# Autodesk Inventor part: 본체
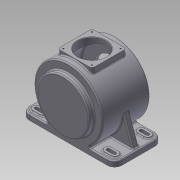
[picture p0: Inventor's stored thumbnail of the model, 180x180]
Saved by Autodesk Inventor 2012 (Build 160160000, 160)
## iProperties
Created: 2015-06
Part Number: 본체
Material: 알루미늄-6061
Document SubType Name: Modeling
Designer: Administrator
Density: 2.71 g/cm^3
Mass: 3279.03 g
Surface Area: 2317.29 cm^2
Volume: 1209.97 cm^3
Author: Administrator
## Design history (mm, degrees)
sketch "스케치1"
  geometry: L1 (0, -59)-(115, -59); L2 (115, -59)-(115, 59); L3 (115, 59)-(-115, 59); L4 (-115, 59)-(-115, -59); L5 (-115, -59)-(0, -59); 1 further point
  constraints: 10 end point, 1 collinear, 1 parallel, 1 perpendicular, 1 point on line
  dimensions: "d7" = 118 distance of L1.end L2.end; "d8" = 230 distance of L2.end L3.end; "d9" = 118 distance of L3.end L4.end
extrude "돌출1" new body sketch "스케치1" distance "d10" = 14; taper "d11" = 0 deg
sketch "스케치2"
  geometry: C1 r 85 at (0, 85); 1 further point
  constraints: 1 centre point
  dimensions: "d13" = 170 diameter of C1
extrude "돌출2" join sketch "스케치2" stored distance "d14" = 118; taper "d15" = 0 deg
sketch "스케치3"
  geometry: C1 r 77 at (0, 85); 1 further point
  constraints: 1 centre point
extrude "돌출3" cut sketch "스케치3" stored distance "d20" = 102; taper "d21" = 0 deg
sketch "스케치4"
  geometry: C1 r 65 at (115, -85); A1 r 85 centre (115, -85) between (68.267, -14) and (161.733, -14) reference; 1 further point
  constraints: 1 centre point, 1 coincident
  dimensions: "d22" = 130 diameter of C1
extrude "돌출4" join sketch "스케치4" distance "d23" = 3; taper "d24" = 0 deg
sketch "스케치5"
  geometry: C1 r 65 at (0, 0) reference; C2 r 47.5 at (0, 0); 1 further point
  constraints: 1 centre point, 1 coincident
  dimensions: "d25" = 95 diameter of C2
extrude "돌출5" cut sketch "스케치5" distance "d26" = 30; taper "d27" = 0 deg
sketch "스케치6"
  geometry: C1 r 65 at (115, 85); A1 r 85 centre (115, 85) between (161.733, 14) and (68.267, 14) reference; 1 further point
  constraints: 1 centre point, 1 coincident
  dimensions: "d28" = 130 diameter of C1
extrude "돌출6" join sketch "스케치6" distance "d29" = 13; taper "d30" = 0 deg
node "작업 평면1"
sketch "스케치7"
  geometry: C1 r 31 at (0, 85); 1 further point
  constraints: 1 centre point
  dimensions: "d33" = 62 diameter of C1
extrude "돌출7" join sketch "스케치7" distance "d34" = 3.5; taper "d35" = -25 deg
sketch "스케치8"
  geometry: C1 r 29.368 at (0, 0) reference; C2 r 23.5 at (0, 0); 1 further point
  constraints: 1 centre point, 1 coincident
  dimensions: "d36" = 47 diameter of C2
extrude "돌출8" cut sketch "스케치8" distance "d37" = 14; taper "d38" = 0 deg
sketch "스케치9"
  geometry: C1 r 23.5 at (0, 0) reference; C2 r 15 at (0, 0); 1 further point
  constraints: 1 centre point, 1 coincident
  dimensions: "d39" = 30 diameter of C2
extrude "돌출9" cut sketch "스케치9" distance "d40" = 3; taper "d41" = 0 deg
node "작업 평면2"
sketch "스케치10"
  geometry: L1 (0, 42.5)-(-42.5, 42.5); L2 (-42.5, 42.5)-(-42.5, -42.5); L3 (-42.5, -42.5)-(42.5, -42.5); L4 (42.5, -42.5)-(42.5, 42.5); L5 (42.5, 42.5)-(0, 42.5); 1 further point
  constraints: 10 end point, 1 parallel, 1 perpendicular
  dimensions: "d44" = 42.5 distance of L1.start L1.end; "d45" = 85 distance of L1.end L2.end; "d46" = 85 distance of L2.end L3.end; "d47" = 85 distance of L3.end L4.end
extrude "돌출10" join sketch "스케치10" stored distance "d48" = 3; taper "d49" = 0 deg
sketch "스케치11"
  geometry: C1 r 35 at (0, 0); 1 further point
  constraints: 1 centre point, 1 coincident
  dimensions: "d50" = 70 diameter of C1
extrude "돌출11" cut sketch "스케치11" distance "d51" = 30; taper "d52" = 0 deg
sketch "스케치12"
  geometry: L1 (115, 59)-(-115, 59) reference; L2 (115, -59)-(115, 59) reference; L3 (-115, -59)-(115, -59) reference; L4 (-115, 59)-(-115, -59) reference; L5 (81, 50)-(97, 50); L6 (81, 32)-(97, 32); L7 (81, -50)-(97, -50); L8 (81, -32)-(97, -32); L9 (-81, 50)-(-97, 50); L10 (-81, 32)-(-97, 32); L11 (-81, -32)-(-97, -32); L12 (-81, -50)-(-97, -50); A1 r 9 centre (81, 41) between (81, 50) and (81, 32); A2 r 9 centre (97, 41) between (97, 32) and (97, 50); A3 r 9 centre (81, -41) between (81, -32) and (81, -50); A4 r 9 centre (97, -41) between (97, -50) and (97, -32); A5 r 9 centre (-81, 41) between (-81, 32) and (-81, 50); A6 r 9 centre (-97, 41) between (-97, 50) and (-97, 32); A7 r 9 centre (-81, -41) between (-81, -50) and (-81, -32); A8 r 9 centre (-97, -41) between (-97, -32) and (-97, -50); 1 further point
  constraints: 16 end point, 16 point on circle, 8 centre point, 3 tangent, 1 parallel
extrude "돌출12" join sketch "스케치12" distance "d59" = 3; taper "d60" = 0 deg
sketch "스케치13"
  geometry: L1 (81, -37)-(97, -37); L2 (81, -45)-(97, -45); L3 (81, 37)-(97, 37); L4 (81, 45)-(97, 45); L5 (-81, 45)-(-97, 45); L6 (-81, 37)-(-97, 37); L7 (-81, -37)-(-97, -37); L8 (-81, -45)-(-97, -45); A1 r 9 centre (81, -41) between (81, -32) and (81, -50) reference; A2 r 9 centre (97, -41) between (97, -50) and (97, -32) reference; A3 r 4 centre (81, -41) between (81, -37) and (81, -45); A4 r 4 centre (97, -41) between (97, -45) and (97, -37); A5 r 4 centre (81, 41) between (81, 45) and (81, 37); A6 r 4 centre (97, 41) between (97, 37) and (97, 45); A7 r 4 centre (-81, 41) between (-81, 37) and (-81, 45); A8 r 4 centre (-97, 41) between (-97, 45) and (-97, 37); A9 r 4 centre (-81, -41) between (-81, -45) and (-81, -37); A10 r 4 centre (-97, -41) between (-97, -37) and (-97, -45); 3 further points
  constraints: 16 end point, 16 point on circle, 8 centre point, 4 coincident, 2 tangent
extrude "돌출13" cut sketch "스케치13" distance "d63" = 50; taper "d64" = 0 deg
sketch "스케치14"
  geometry: L1 (115, 0)-(-115, 0) reference; L2 (-115, 0)-(-115, 14) reference; L3 (-115, 14)-(-46.733, 14) reference; L4 (46.733, 14)-(115, 14) reference; L5 (115, 0)-(115, 14) reference; L6 (-109, 14)-(-81.24, 90.27); L7 (-81.24, 90.27)-(-78.742, 68.078); L8 (-78.742, 68.078)-(-72.572, 46.827); L9 (-72.572, 46.827)-(-60.461, 31.517); L10 (-60.461, 31.517)-(-46.733, 17.578); L11 (-109, 14)-(-41.495, 14); L12 (-41.495, 14)-(-46.733, 17.578); C1 r 65 at (0, 85) reference; A1 r 85 centre (0, 85) between (46.733, 14) and (-46.733, 14) reference; 1 further point
  constraints: 14 end point, 1 perpendicular, 1 point on line
extrude "돌출14" join sketch "스케치14" stored distance "d67" = 15; taper "d68" = 0 deg
sketch "스케치15"
  geometry: 2 further points
hole "구멍1" sketch "스케치15" at (0, -55) diameter "d70" = 3.242; stored, may be unused: countersink angle "d74" = 90 deg, drill point angle "d76" = 118 deg; dims "d71" = 20, "d72" = 4, "d73" = 2, "d75" = 20
sketch "스케치16"
  geometry: 1 further point
hole "구멍2" sketch "스케치16" at (-35.5, 35.5) diameter "d82" = 3.242; stored, may be unused: countersink angle "d86" = 90 deg, drill point angle "d88" = 118 deg; dims "d83" = 10, "d84" = 4, "d85" = 2, "d87" = 13
sketch "스케치17"
  geometry: 3 further points
hole "구멍3" sketch "스케치17" at (35.5, 35.5), (35.5, -35.5), (-35.5, -35.5) diameter "d92" = 3.242; stored, may be unused: countersink angle "d96" = 90 deg, drill point angle "d98" = 118 deg; dims "d93" = 10, "d94" = 4, "d95" = 2, "d97" = 13
fillet "모깎기3" dims "d115" = 3
chamfer "모따기1" distance "d108" = 1; stored, may be unused: second distance "d109" = 2, angle "d110" = 45 deg
sketch "스케치18"
  geometry: L1 (0, 85)-(77.036, 120.923); A1 r 85 centre (0, 85) between (53.953, 19.318) and (-53.953, 19.318) reference; 2 further points
  constraints: 2 end point, 1 coincident, 1 point on circle
node "작업 평면4"
sketch "스케치19"
  geometry: 2 further points
  constraints: 1 other
feature "엠보싱1" sketch "스케치19" dims "d7" = 118, "d8" = 230, "d9" = 118, "d22" = 130, "d113" = 0.5, "d114" = 0
node "솔리드1"
pattern_circular "원형 패턴1" dims angle "d78" = 360 deg
mirror "대칭1"
fillet "모깎기1" dims "d104" = 3, "d105" = 0.3
fillet "모깎기2" dims "d106" = 7, "d107" = 18, "d116" = 3
node "투영된 루프1"
node "투영된 루프2"
other parameters: "d31" = -51, "d42" = 173
